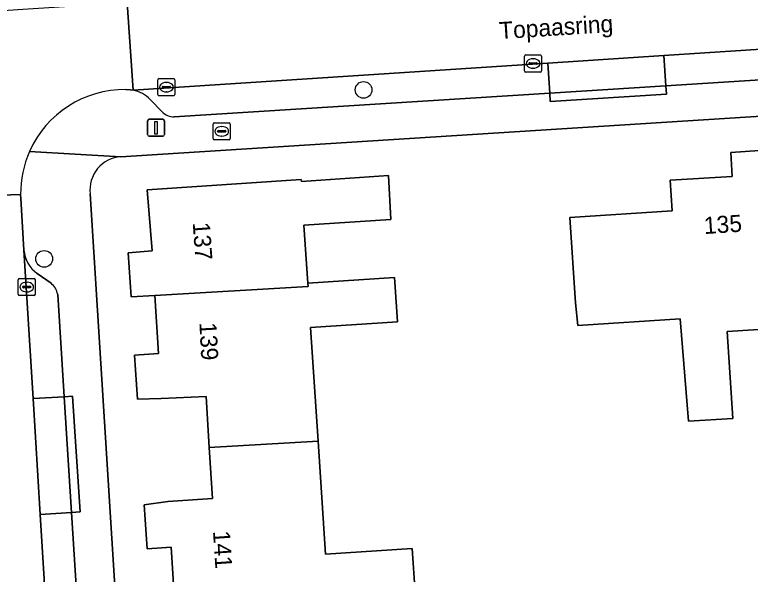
# Model space of a CAD drawing. Extents: x 159626 to 160723, y 388173 to 389416.
# Drawn here: x 160262.39 to 160305.5, y 388380.87 to 388413.65 of the extents above; entities that cross this region are included whole.
import ezdxf

# ---------------------------------------------------------------- set-up
doc = ezdxf.new("R2010")
doc.units = 0
for name, color, linetype in [('IMGEO_Boom', 7, 'Continuous'), ('IMGEO_Brandkraan', 7, 'Continuous'), ('IMGEO_Erf', 7, 'Continuous'), ('IMGEO_Kolk', 7, 'Continuous'), ('IMGEO_Lichtmast', 7, 'Continuous'), ('IMGEO_Openbare_ruimte_label', 7, 'Continuous'), ('IMGEO_Pand', 7, 'Continuous'), ('IMGEO_Pand_nummerreeks', 7, 'Continuous'), ('IMGEO_Parkeervlak_open', 7, 'Continuous'), ('IMGEO_Rijbaan_lokaal_open', 7, 'Continuous'), ('IMGEO_Voetpad_open', 7, 'Continuous')]:
    doc.layers.add(name, color=color, linetype=linetype)

msp = doc.modelspace()

# ---------------------------------------------------------------- linework, layer by layer
at = {"layer": 'IMGEO_Boom'}
for centre in [(160282.842, 388409.245), (160264.121, 388399.348)]:
    msp.add_circle(centre, 0.489, dxfattribs=at)
at = {"layer": 'IMGEO_Brandkraan'}
for p, q in [((160274.103, 388407.317), (160274.955, 388407.317)), ((160274.028, 388406.391), (160274.028, 388407.243)), ((160274.516, 388407.097), (160274.541, 388407.097)), ((160275.029, 388407.243), (160275.029, 388406.391)), ((160274.287, 388406.811), (160274.287, 388406.823)), ((160274.725, 388406.774), (160274.327, 388406.774)), ((160274.33, 388406.86), (160274.728, 388406.86)), ((160274.539, 388406.537), (160274.514, 388406.537)), ((160274.771, 388406.823), (160274.771, 388406.811)), ((160274.955, 388406.317), (160274.103, 388406.317))]:
    msp.add_line(p, q, dxfattribs=at)
for points in [[(160274.103, 388407.317), (160274.955, 388407.317)], [(160274.028, 388406.391), (160274.028, 388407.243)], [(160275.029, 388407.243), (160275.029, 388406.391)], [(160274.955, 388406.317), (160274.103, 388406.317)]]:
    msp.add_lwpolyline(points, dxfattribs=at)
for centre, radius, start, end in [((160274.105, 388407.241), 0.0765, 91.552, 178.448), ((160274.105, 388407.241), 0.0765, 91.552, 178.448), ((160274.953, 388407.241), 0.0765, 1.552, 88.448), ((160274.953, 388407.241), 0.0765, 1.552, 88.448), ((160274.327, 388406.82), 0.0403, 85.8775, 175.7526), ((160274.324, 388406.81), 0.0366, 178.938, 274.7102), ((160274.728, 388406.817), 0.043, 264.8664, 352.4533), ((160274.732, 388406.822), 0.0386, 1.7309, 96.639), ((160274.105, 388406.393), 0.0765, 181.552, 268.448), ((160274.105, 388406.393), 0.0765, 181.552, 268.448), ((160274.953, 388406.393), 0.0765, 271.552, 358.448), ((160274.953, 388406.393), 0.0765, 271.552, 358.448)]:
    msp.add_arc(centre, radius, start, end, dxfattribs=at)
for centre, major_axis, ratio, start_param, end_param in [((160274.515, 388406.817), (-0.387, 0.002), 0.722429, 4.712389, 7.853982), ((160274.54, 388406.817), (-0.39, 0.002), 0.717154, 1.570796, 4.712389)]:
    msp.add_ellipse(centre, major_axis=major_axis, ratio=ratio, start_param=start_param, end_param=end_param, dxfattribs=at)
at = {"layer": 'IMGEO_Erf'}
for points in [[(160359.06, 388411.068), (160268.623, 388405.331)], [(160307.539, 388395.302), (160304.144, 388395.086), (160304.469, 388389.994), (160301.874, 388389.829), (160301.391, 388395.832), (160295.4, 388395.45), (160295.268, 388396.78), (160294.925, 388401.768), (160300.919, 388402.158), (160300.802, 388403.956), (160304.447, 388404.176), (160304.362, 388405.57), (160306.891, 388405.756)], [(160271.773, 388379.044), (160271.555, 388382.454), (160270.15, 388382.364), (160269.982, 388384.946), (160271.373, 388385.134), (160273.99, 388385.299), (160273.799, 388388.298), (160273.608, 388391.293), (160270.986, 388391.175), (160269.584, 388391.136), (160269.422, 388393.713), (160270.823, 388393.801), (160270.612, 388397.194), (160269.211, 388397.115), (160269.047, 388399.699), (160270.456, 388399.816), (160270.161, 388403.397), (160279.183, 388403.99), (160279.196, 388403.887), (160284.293, 388404.237), (160284.44, 388401.65), (160279.347, 388401.317), (160279.57, 388397.922), (160284.661, 388398.254), (160284.678, 388397.99), (160284.83, 388395.658), (160279.738, 388395.324), (160280.173, 388388.659), (160280.605, 388382.055), (160285.696, 388382.388), (160285.866, 388379.791)], [(160266.819, 388403.153), (160268.933, 388369.604)]]:
    msp.add_lwpolyline(points, dxfattribs=at)
msp.add_arc((160268.745, 388403.394), 1.941, 93.5933, 187.138, dxfattribs=at)
at = {"layer": 'IMGEO_Kolk'}
for p, q in [((160292.272, 388410.366), (160292.272, 388411.218)), ((160292.347, 388411.292), (160293.199, 388411.292)), ((160293.273, 388411.218), (160293.273, 388410.366)), ((160292.531, 388410.786), (160292.531, 388410.798)), ((160292.969, 388410.749), (160292.571, 388410.749)), ((160292.574, 388410.835), (160292.972, 388410.835)), ((160292.76, 388411.072), (160292.785, 388411.072)), ((160293.015, 388410.798), (160293.015, 388410.786)), ((160292.783, 388410.512), (160292.758, 388410.512)), ((160270.859, 388409.906), (160271.711, 388409.906)), ((160293.199, 388410.292), (160292.347, 388410.292)), ((160270.784, 388408.98), (160270.784, 388409.832)), ((160271.086, 388409.449), (160271.484, 388409.449)), ((160271.272, 388409.686), (160271.297, 388409.686)), ((160271.785, 388409.832), (160271.785, 388408.98)), ((160271.043, 388409.4), (160271.043, 388409.412)), ((160271.481, 388409.363), (160271.083, 388409.363)), ((160271.295, 388409.126), (160271.27, 388409.126)), ((160271.527, 388409.412), (160271.527, 388409.4)), ((160271.711, 388408.906), (160270.859, 388408.906)), ((160262.602, 388397.269), (160262.602, 388398.121)), ((160262.677, 388398.195), (160263.529, 388398.195)), ((160263.09, 388397.975), (160263.115, 388397.975)), ((160263.603, 388398.121), (160263.603, 388397.269)), ((160262.861, 388397.689), (160262.861, 388397.701)), ((160263.299, 388397.652), (160262.901, 388397.652)), ((160262.904, 388397.738), (160263.302, 388397.738)), ((160263.113, 388397.415), (160263.088, 388397.415)), ((160263.345, 388397.701), (160263.345, 388397.689)), ((160263.529, 388397.195), (160262.677, 388397.195))]:
    msp.add_line(p, q, dxfattribs=at)
for points in [[(160292.272, 388410.366), (160292.272, 388411.218)], [(160292.347, 388411.292), (160293.199, 388411.292)], [(160293.273, 388411.218), (160293.273, 388410.366)], [(160270.859, 388409.906), (160271.711, 388409.906)], [(160293.199, 388410.292), (160292.347, 388410.292)], [(160270.784, 388408.98), (160270.784, 388409.832)], [(160271.785, 388409.832), (160271.785, 388408.98)], [(160271.711, 388408.906), (160270.859, 388408.906)], [(160262.602, 388397.269), (160262.602, 388398.121)], [(160262.677, 388398.195), (160263.529, 388398.195)], [(160263.603, 388398.121), (160263.603, 388397.269)], [(160263.529, 388397.195), (160262.677, 388397.195)]]:
    msp.add_lwpolyline(points, dxfattribs=at)
for centre, radius, start, end in [((160292.349, 388411.216), 0.0765, 91.552, 178.448), ((160292.349, 388411.216), 0.0765, 91.552, 178.448), ((160293.197, 388411.216), 0.0765, 1.552, 88.448), ((160293.197, 388411.216), 0.0765, 1.552, 88.448), ((160292.571, 388410.795), 0.0403, 85.8775, 175.7526), ((160292.568, 388410.785), 0.0366, 178.938, 274.7102), ((160292.972, 388410.792), 0.043, 264.8664, 352.4533), ((160292.976, 388410.797), 0.0386, 1.7309, 96.639), ((160292.349, 388410.368), 0.0765, 181.552, 268.448), ((160292.349, 388410.368), 0.0765, 181.552, 268.448), ((160293.197, 388410.368), 0.0765, 271.552, 358.448), ((160293.197, 388410.368), 0.0765, 271.552, 358.448), ((160270.861, 388409.83), 0.0765, 91.552, 178.448), ((160270.861, 388409.83), 0.0765, 91.552, 178.448), ((160271.709, 388409.83), 0.0765, 1.552, 88.448), ((160271.709, 388409.83), 0.0765, 1.552, 88.448), ((160271.083, 388409.409), 0.0403, 85.8775, 175.7526), ((160271.488, 388409.411), 0.0386, 1.7309, 96.639), ((160271.08, 388409.399), 0.0366, 178.938, 274.7102), ((160271.484, 388409.406), 0.043, 264.8664, 352.4533), ((160270.861, 388408.982), 0.0765, 181.552, 268.448), ((160270.861, 388408.982), 0.0765, 181.552, 268.448), ((160271.709, 388408.982), 0.0765, 271.552, 358.448), ((160271.709, 388408.982), 0.0765, 271.552, 358.448), ((160262.679, 388398.119), 0.0765, 91.552, 178.448), ((160262.679, 388398.119), 0.0765, 91.552, 178.448), ((160263.527, 388398.119), 0.0765, 1.552, 88.448), ((160263.527, 388398.119), 0.0765, 1.552, 88.448), ((160262.901, 388397.698), 0.0403, 85.8775, 175.7526), ((160262.898, 388397.688), 0.0366, 178.938, 274.7102), ((160263.302, 388397.695), 0.043, 264.8664, 352.4533), ((160263.306, 388397.7), 0.0386, 1.7309, 96.639), ((160262.679, 388397.271), 0.0765, 181.552, 268.448), ((160262.679, 388397.271), 0.0765, 181.552, 268.448), ((160263.527, 388397.271), 0.0765, 271.552, 358.448), ((160263.527, 388397.271), 0.0765, 271.552, 358.448)]:
    msp.add_arc(centre, radius, start, end, dxfattribs=at)
for centre, major_axis, ratio, start_param, end_param in [((160292.759, 388410.792), (-0.387, 0.002), 0.722429, 4.712389, 7.853982), ((160292.784, 388410.792), (-0.39, 0.002), 0.717154, 1.570796, 4.712389), ((160271.271, 388409.406), (-0.387, 0.002), 0.722429, 4.712389, 7.853982), ((160271.296, 388409.406), (-0.39, 0.002), 0.717154, 1.570796, 4.712389), ((160263.089, 388397.695), (-0.387, 0.002), 0.722429, 4.712389, 7.853982), ((160263.114, 388397.695), (-0.39, 0.002), 0.717154, 1.570796, 4.712389)]:
    msp.add_ellipse(centre, major_axis=major_axis, ratio=ratio, start_param=start_param, end_param=end_param, dxfattribs=at)
at = {"layer": 'IMGEO_Lichtmast'}
for p, q in [((160270.181, 388406.626), (160270.181, 388407.426)), ((160270.181, 388407.426), (160270.181, 388406.626)), ((160270.281, 388407.526), (160271.071, 388407.526)), ((160271.071, 388407.526), (160270.281, 388407.526)), ((160271.171, 388407.426), (160271.171, 388406.626)), ((160271.171, 388406.626), (160271.171, 388407.426)), ((160271.071, 388406.526), (160270.281, 388406.526)), ((160270.281, 388406.526), (160271.071, 388406.526))]:
    msp.add_line(p, q, dxfattribs=at)
msp.add_lwpolyline([(160270.601, 388407.401), (160270.751, 388407.401), (160270.751, 388406.651), (160270.601, 388406.651), (160270.601, 388407.401)], dxfattribs=at)
for centre, start, end in [((160270.281, 388407.426), 90, 180), ((160270.281, 388407.426), 90, 180), ((160271.071, 388407.426), 0, 90), ((160271.071, 388407.426), 360, 90), ((160270.281, 388406.626), 180, 270), ((160270.281, 388406.626), 180, 270), ((160271.071, 388406.626), 270, 0), ((160271.071, 388406.626), 270, 0)]:
    msp.add_arc(centre, 0.1, start, end, dxfattribs=at)
at = {"layer": 'IMGEO_Pand'}
for points in [[(160306.977, 388404.361), (160306.891, 388405.756), (160304.362, 388405.57), (160304.447, 388404.176), (160300.802, 388403.956), (160300.919, 388402.158), (160294.925, 388401.768), (160295.268, 388396.78), (160295.4, 388395.45), (160301.391, 388395.832), (160301.874, 388389.829), (160304.469, 388389.994), (160304.144, 388395.086), (160307.539, 388395.302)], [(160279.347, 388401.317), (160284.44, 388401.65), (160284.293, 388404.237), (160279.196, 388403.887), (160279.183, 388403.99), (160270.161, 388403.397), (160270.456, 388399.816), (160269.047, 388399.699), (160269.211, 388397.115), (160270.612, 388397.194), (160279.584, 388397.723), (160279.57, 388397.922)], [(160279.738, 388395.324), (160284.83, 388395.658), (160284.678, 388397.99), (160284.661, 388398.254), (160279.57, 388397.922), (160279.584, 388397.723), (160270.612, 388397.194), (160270.823, 388393.801), (160269.422, 388393.713), (160269.584, 388391.136), (160270.986, 388391.175), (160273.608, 388391.293), (160273.799, 388388.298), (160280.173, 388388.659)], [(160273.799, 388388.298), (160273.99, 388385.299), (160271.373, 388385.134), (160269.982, 388384.946), (160270.15, 388382.364), (160271.555, 388382.454), (160271.773, 388379.044), (160280.773, 388379.458), (160285.866, 388379.791), (160285.696, 388382.388), (160280.605, 388382.055), (160280.173, 388388.659)]]:
    msp.add_lwpolyline(points, close=True, dxfattribs=at)
at = {"layer": 'IMGEO_Parkeervlak_open'}
for points in [[(160312.452, 388412.041), (160300.438, 388411.258), (160300.553, 388409.489), (160312.554, 388410.243)], [(160300.438, 388411.258), (160293.631, 388410.814), (160293.745, 388409.062), (160300.553, 388409.489)], [(160265.297, 388391.273), (160263.472, 388391.159), (160263.888, 388384.375), (160265.731, 388384.491)], [(160265.731, 388384.491), (160263.888, 388384.375), (160264.604, 388372.685), (160266.46, 388372.8)]]:
    msp.add_lwpolyline(points, close=True, dxfattribs=at)
for points in [[(160293.631, 388410.814), (160269.34, 388409.231)], [(160271.733, 388407.659), (160293.745, 388409.062), (160293.631, 388410.814)], [(160270.33, 388408.676), (160271.028, 388407.965)], [(160262.939, 388399.866), (160263.472, 388391.159), (160265.297, 388391.273), (160264.913, 388397.262)], [(160264.525, 388397.917), (160263.709, 388398.499)]]:
    msp.add_lwpolyline(points, dxfattribs=at)
for centre, radius, start, end in [((160268.995, 388407.456), 1.808, 42.4349, 79.0146), ((160271.789, 388408.752), 1.095, 225.9881, 267.0862), ((160264.753, 388399.987), 1.818, 183.8243, 234.9588), ((160263.836, 388397.067), 1.094, 10.283, 50.9992)]:
    msp.add_arc(centre, radius, start, end, dxfattribs=at)
at = {"layer": 'IMGEO_Rijbaan_lokaal_open'}
for points in [[(160323.643, 388417.859), (160317.448, 388417.46), (160302.231, 388416.481), (160298.471, 388416.239), (160292.484, 388415.854), (160288.721, 388415.612), (160282.729, 388415.226), (160278.975, 388414.984), (160272.626, 388414.576), (160268.981, 388414.341), (160269.34, 388409.231), (160293.631, 388410.814), (160300.438, 388411.258), (160312.452, 388412.041), (160319.213, 388412.481), (160324.121, 388412.801)], [(160263.888, 388384.375), (160263.472, 388391.159), (160262.939, 388399.866), (160262.754, 388402.884), (160262.743, 388403.122), (160257.606, 388402.94), (160257.626, 388402.645), (160257.87, 388399.162), (160257.882, 388398.984), (160259.821, 388370.173), (160260.059, 388366.386), (160260.22, 388363.817), (160261.446, 388344.248), (160261.476, 388343.786), (160266.356, 388344.094), (160265.123, 388364.216), (160264.836, 388368.907), (160264.604, 388372.685)]]:
    msp.add_lwpolyline(points, close=True, dxfattribs=at)
for points in [[(160268.903, 388409.261), (160269.168, 388409.243), (160269.34, 388409.231), (160268.981, 388414.341), (160268.676, 388414.321), (160262.869, 388413.948), (160259.126, 388413.707), (160252.536, 388413.289), (160249.091, 388413.07), (160249.493, 388407.916), (160252.291, 388407.988)], [(160257.577, 388403.35), (160257.606, 388402.94), (160262.743, 388403.122)]]:
    msp.add_lwpolyline(points, dxfattribs=at)
for centre, radius, start, end in [((160268.827, 388403.177), 6.084, 89.281, 156.1022), ((160268.836, 388403.176), 6.094, 156.1294, 180.5084)]:
    msp.add_arc(centre, radius, start, end, dxfattribs=at)
at = {"layer": 'IMGEO_Voetpad_open'}
for points in [[(160263.264, 388405.642), (160268.623, 388405.331), (160359.06, 388411.068), (160365.311, 388411.469), (160407.414, 388414.173)], [(160346.334, 388412.396), (160337.505, 388411.821), (160337.537, 388411.323), (160330.753, 388410.881), (160330.721, 388411.379), (160327.068, 388411.151), (160324.293, 388410.977), (160319.331, 388410.667), (160319.362, 388410.173), (160312.585, 388409.744), (160312.554, 388410.243), (160300.553, 388409.489), (160300.584, 388408.992), (160293.776, 388408.563), (160293.745, 388409.062), (160271.733, 388407.659)], [(160269.34, 388409.231), (160269.168, 388409.243), (160268.903, 388409.261)], [(160271.028, 388407.965), (160270.33, 388408.676)], [(160268.623, 388405.331), (160263.264, 388405.642)], [(160262.743, 388403.122), (160262.754, 388402.884), (160262.939, 388399.866)], [(160269.005, 388368.466), (160268.933, 388369.604), (160266.819, 388403.153)], [(160263.709, 388398.499), (160264.525, 388397.917)], [(160264.913, 388397.262), (160265.297, 388391.273), (160265.785, 388391.304), (160266.229, 388384.523), (160265.731, 388384.491), (160266.46, 388372.8), (160266.958, 388372.832), (160267.206, 388369.055), (160266.703, 388369.023), (160266.83, 388367.041)]]:
    msp.add_lwpolyline(points, dxfattribs=at)
for points in [[(160293.745, 388409.062), (160293.776, 388408.563), (160300.584, 388408.992), (160300.553, 388409.489)], [(160265.731, 388384.491), (160266.229, 388384.523), (160265.785, 388391.304), (160265.297, 388391.273)]]:
    msp.add_lwpolyline(points, close=True, dxfattribs=at)
for centre, radius, start, end in [((160268.827, 388403.177), 6.084, 89.281, 156.1022), ((160268.995, 388407.456), 1.808, 42.4349, 79.0146), ((160271.789, 388408.752), 1.095, 225.9881, 267.0862), ((160268.836, 388403.176), 6.094, 156.1294, 180.5084), ((160268.745, 388403.394), 1.941, 93.5933, 187.138), ((160264.753, 388399.987), 1.818, 183.8243, 234.9588), ((160263.836, 388397.067), 1.094, 10.283, 50.9992)]:
    msp.add_arc(centre, radius, start, end, dxfattribs=at)

# ---------------------------------------------------------------- texts
at = {"layer": 'IMGEO_Openbare_ruimte_label'}
msp.add_text('Topaasring', height=1, rotation=3.6693, dxfattribs=at).set_placement((160290.816, 388412.216))
at = {"layer": 'IMGEO_Pand_nummerreeks'}
for s, rotation, p in [('135', 3.6841, (160302.814, 388400.799)), ('137', 274.1022, (160272.826, 388401.463)), ('139', 272.9906, (160273.217, 388395.604)), ('141', 273.7491, (160274.013, 388383.394))]:
    msp.add_text(s, height=1, rotation=rotation, dxfattribs=at).set_placement(p)

doc.saveas('drawing.dxf')
